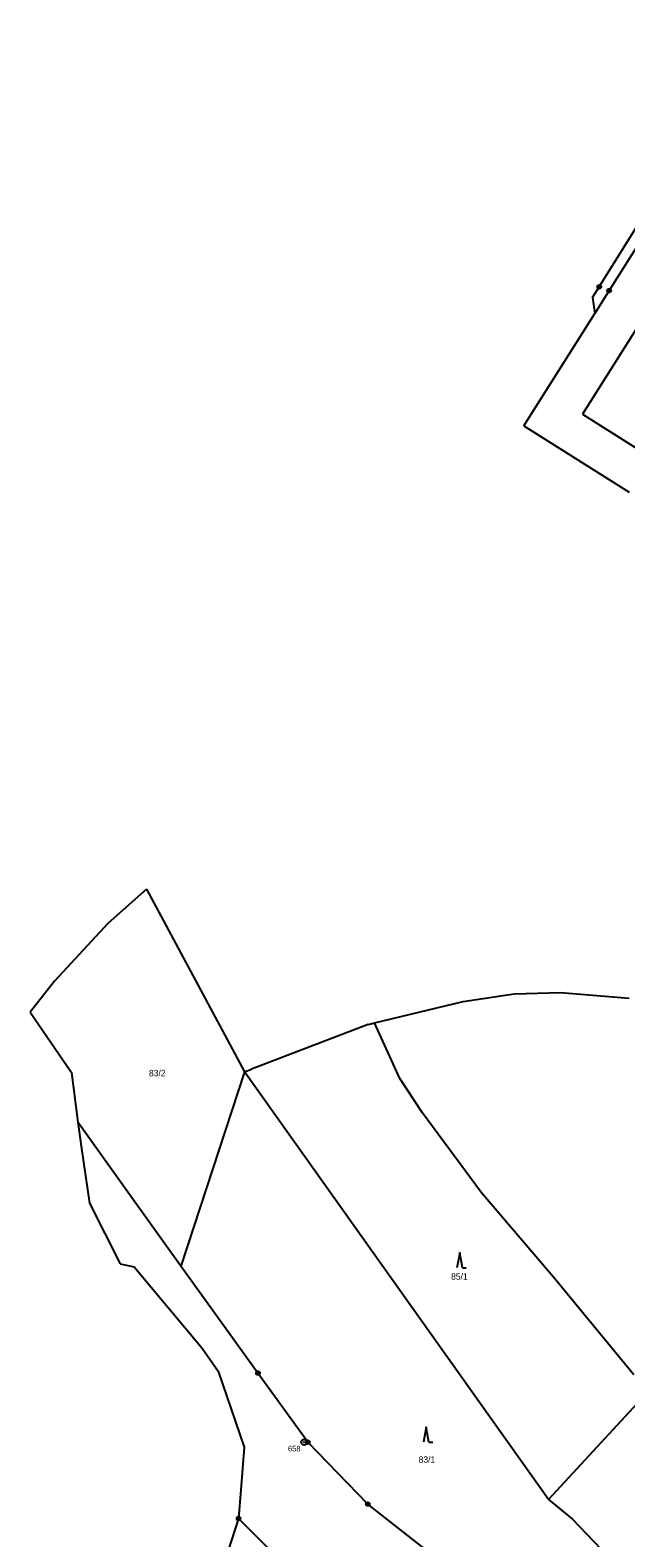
# Model space of a CAD drawing. Extents: x -645290 to -643454, y -1064771 to -1062356.
# Drawn here: x -645290.3 to -645131.3, y -1063586.8 to -1063184.2 of the extents above; entities that cross this region are included whole.
import ezdxf
from ezdxf.enums import TextEntityAlignment as Align

# ---------------------------------------------------------------- set-up
doc = ezdxf.new("R2010")
doc.units = 0
doc.header["$LTSCALE"] = 0.68
for name, color, linetype, lineweight in [('1', 7, 'Continuous', 25), ('3', 7, 'Continuous', 25), ('8', 7, 'Continuous', 25)]:
    doc.layers.add(name, color=color, linetype=linetype, lineweight=lineweight)
doc.layers.add('2', color=7, linetype='Continuous')

msp = doc.modelspace()

# ---------------------------------------------------------------- linework, layer by layer
at = {"layer": '1'}
for p, q in [((-645078.17, -1063184.25), (-645142.88, -1063286.77)), ((-645138.37, -1063252.79), (-645097.97, -1063187.78)), ((-645095.5, -1063189.97), (-645135.74, -1063253.8)), ((-645140.17, -1063255.68), (-645138.37, -1063252.79)), ((-645135.74, -1063253.8), (-645139.6, -1063259.93)), ((-645140.17, -1063255.68), (-645139.6, -1063259.93)), ((-645158.52, -1063289.93), (-645139.6, -1063259.93)), ((-645142.88, -1063286.77), (-645060.68, -1063338.7)), ((-645158.52, -1063289.93), (-645130.42, -1063307.64)), ((-645259.26, -1063413.59), (-645269.56, -1063422.78)), ((-645259.26, -1063413.59), (-645233.07, -1063462.4)), ((-645269.56, -1063422.78), (-645283.79, -1063438.23)), ((-645283.79, -1063438.23), (-645290.33, -1063446.44)), ((-645198.41, -1063449.32), (-645174.73, -1063443.64)), ((-645174.73, -1063443.64), (-645161.06, -1063441.58)), ((-645161.06, -1063441.58), (-645148.74, -1063441.26)), ((-645148.74, -1063441.26), (-645130.42, -1063442.72)), ((-645290.33, -1063446.44), (-645279.3, -1063462.62)), ((-645200.1, -1063449.72), (-645231.2, -1063461.68)), ((-645200.1, -1063449.72), (-645198.41, -1063449.32)), ((-645191.67, -1063464.19), (-645198.41, -1063449.32)), ((-645279.3, -1063462.62), (-645277.64, -1063475.82)), ((-645233.07, -1063462.4), (-645250.06, -1063514.27)), ((-645233.07, -1063462.4), (-645231.2, -1063461.68)), ((-645151.96, -1063576.63), (-645233.07, -1063462.4)), ((-645185.64, -1063473.22), (-645191.67, -1063464.19)), ((-645277.64, -1063475.82), (-645276.62, -1063482.87)), ((-645262.9, -1063496.41), (-645277.64, -1063475.82)), ((-645169.84, -1063494.73), (-645185.64, -1063473.22)), ((-645276.62, -1063482.87), (-645274.52, -1063497.45)), ((-645250.06, -1063514.27), (-645262.9, -1063496.41)), ((-645150.65, -1063517.12), (-645169.84, -1063494.73)), ((-645274.52, -1063497.45), (-645266.28, -1063513.63)), ((-645266.28, -1063513.63), (-645262.6, -1063514.43)), ((-645262.6, -1063514.43), (-645244.39, -1063536.16)), ((-645229.51, -1063542.83), (-645250.06, -1063514.27)), ((-645129.15, -1063543.34), (-645150.65, -1063517.12)), ((-645244.39, -1063536.16), (-645240.15, -1063542.33)), ((-645240.15, -1063542.33), (-645233.23, -1063562.62)), ((-645216.21, -1063561.29), (-645229.51, -1063542.83)), ((-645127.2, -1063549.82), (-645151.96, -1063576.63)), ((-645233.23, -1063562.62), (-645234.1, -1063574)), ((-645200.19, -1063577.83), (-645216.21, -1063561.29)), ((-645234.1, -1063574), (-645234.68, -1063581.63)), ((-645151.96, -1063576.63), (-645145.5, -1063581.86)), ((-645183.2, -1063591.19), (-645200.19, -1063577.83)), ((-645234.68, -1063581.63), (-645245.04, -1063613.82)), ((-645223.98, -1063592.42), (-645234.68, -1063581.63)), ((-645077.76, -1063652.37), (-645145.5, -1063581.86))]:
    msp.add_line(p, q, dxfattribs=at)
at = {"layer": '3'}
for p, q in [((-645174.88, -1063514.77), (-645173.884, -1063514.77)), ((-645183.85, -1063561.31), (-645182.854, -1063561.31))]:
    msp.add_line(p, q, dxfattribs=at)
for points in [[(-645174.88, -1063514.77), (-645175.63, -1063510.77), (-645176.38, -1063514.77)], [(-645183.85, -1063561.31), (-645184.6, -1063557.31), (-645185.35, -1063561.31)]]:
    msp.add_lwpolyline(points, dxfattribs=at)
at = {"layer": '8'}
for centre, radius in [((-645138.37, -1063252.7899), 0.5), ((-645138.37, -1063252.7899), 0.0303), ((-645135.74, -1063253.7999), 0.5), ((-645135.74, -1063253.7999), 0.0303), ((-645229.51, -1063542.8299), 0.5), ((-645229.51, -1063542.8299), 0.0303), ((-645217.2, -1063561.3098), 0.75), ((-645216.21, -1063561.2899), 0.5), ((-645217.2, -1063561.3098), 0.03), ((-645216.21, -1063561.2899), 0.0303), ((-645200.19, -1063577.8299), 0.5), ((-645200.19, -1063577.8299), 0.0303), ((-645234.68, -1063581.6299), 0.5), ((-645234.68, -1063581.6299), 0.0303)]:
    msp.add_circle(centre, radius, dxfattribs=at)

# ---------------------------------------------------------------- texts
at = {"layer": '2'}
for s, p in [('83/2', (-645256.399, -1063463.574)), ('85/1', (-645175.729, -1063517.895)), ('83/1', (-645184.389, -1063566.775))]:
    msp.add_text(s, height=1.7, dxfattribs=at).set_placement(p, align=Align.CENTER)
at = {"layer": '8'}
msp.add_text('658', height=1.5, dxfattribs=at).set_placement((-645221.49, -1063563.754))

doc.saveas('drawing.dxf')
